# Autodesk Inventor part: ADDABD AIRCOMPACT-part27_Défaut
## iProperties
Shininess: 64.0
Length Units: 11269
Angle Units: 11279
Time Units: 11290
Mass Units: 11283
Length Display Precision: 3
Angle Display Precision: 2
Compacted: True
Part Number: ADDABD AIRCOMPACT-part27_Défaut
Document SubType Name: Modeling
Created: 2006-01
Material: Par défaut
Designer: riri
Density: 0.0
Volumn: 0.0
Area: 0.0
PropertySet Name: Model Information
Control State: 0
Master: False
Checked Out: False
Author: riri
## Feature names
1. Base1
